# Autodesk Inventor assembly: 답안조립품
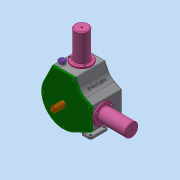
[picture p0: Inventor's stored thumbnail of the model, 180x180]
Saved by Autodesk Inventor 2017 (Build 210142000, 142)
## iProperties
Part Number: 답안조립품
Material: 일반
Document SubType Name: Assembly
Designer: MRC
Author: MRC
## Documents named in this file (13)
- C:\Users\MRC\Desktop\611109V1009\답안조립품.iam
- C:\Users\MRC\Desktop\611109V1009\본체.ipt
- C:\Users\MRC\Desktop\611109V1009\너트 M3.ipt
- C:\Users\MRC\Desktop\611109V1009\베어링 20 x 37 x 9.ipt
- C:\Users\MRC\Desktop\611109V1009\볼트 M3 x 12.ipt
- C:\Users\MRC\Desktop\611109V1009\실린더.ipt
- C:\Users\MRC\Desktop\611109V1009\앞커버.ipt
- C:\Users\MRC\Desktop\611109V1009\축.ipt
- C:\Users\MRC\Desktop\611109V1009\측정게이지.ipt
- C:\Users\MRC\Desktop\611109V1009\커넥팅로드 캡.ipt
- C:\Users\MRC\Desktop\611109V1009\커넥팅로드.ipt
- C:\Users\MRC\Desktop\611109V1009\피스톤 핀.ipt
- C:\Users\MRC\Desktop\611109V1009\피스톤.ipt
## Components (4 placed, 2 different names)
1. 피스톤 핀:1 — 플러쉬:3
2. 피스톤:1 — 플러쉬:1, 플러쉬:4
3. 피스톤:2 — 플러쉬:2, 플러쉬:3
4. 피스톤 핀:2 — 플러쉬:4
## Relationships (4: Flush 4)
- 플러쉬:1 [Flush]: 피스톤:1
- 플러쉬:2 [Flush]: 피스톤:2
- 플러쉬:3 [Flush]: 피스톤 핀:1 ↔ 피스톤:2
- 플러쉬:4 [Flush]: 피스톤:1 ↔ 피스톤 핀:2
